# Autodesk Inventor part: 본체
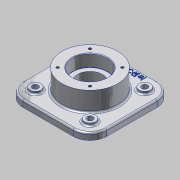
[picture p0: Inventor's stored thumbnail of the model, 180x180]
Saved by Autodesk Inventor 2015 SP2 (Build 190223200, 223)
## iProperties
Created: 2015-07
Part Number: 본체
Material: 알루미늄 6061
Document SubType Name: Modeling
Designer: AMC
Density: 2.7 g/cm^3
Appearance: 알루미늄 - 평지
Author: AMC
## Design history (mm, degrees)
sketch "스케치1"
  geometry: L1 (-75, -75)-(75, -75); L2 (75, -75)-(75, 75); L3 (75, 75)-(-75, 75); L4 (-75, 75)-(-75, -75); L5 (-75, -75)-(75, 75); L6 (75, -75)-(-75, 75); 1 further point
  constraints: 12 end point, 2 midpoint, 2 parallel, 1 horizontal, 1 perpendicular
  dimensions: "d0" = 150 distance of L3.end L2.end; "d1" = 150 distance of L2.end L1.end
extrude "돌출1" new body sketch "스케치1" distance "d2" = 12; taper "d3" = 0 deg
sketch "스케치2"
  geometry: C1 r 50 at (0, 0); 1 further point
  constraints: 1 centre point, 1 coincident
  dimensions: "d4" = 100 diameter of C1
extrude "돌출2" join sketch "스케치2" distance "d5" = 23; taper "d7" = 0 deg; dims "d6" = 47, "d8" = 0
fillet "모깎기1" dims "d9" = 30
sketch "스케치3"
  geometry: L1 (49, -49)-(-49, -49); L2 (-49, -49)-(-49, 49); L3 (-49, 49)-(49, 49); L4 (49, 49)-(49, -49); L5 (49, -49)-(-49, 49); L6 (-49, -49)-(49, 49); C1 r 10 at (-49, 49); 1 further point
  constraints: 12 end point, 2 midpoint, 2 parallel, 1 centre point, 1 coincident, 1 horizontal, 1 perpendicular
  dimensions: "d10" = 98 distance of L2.end L3.end; "d11" = 98 distance of L1.end L2.end; "d12" = 20 diameter of C1
extrude "돌출3" join sketch "스케치3" distance "d13" = 5; taper "d14" = 0 deg
hole "구멍1" diameter "d17" = 11; stored, may be unused: countersink angle "d21" = 90 deg, drill point angle "d23" = 118 deg; dims "d15" = 10, "d16" = 10, "d18" = 6, "d19" = 4, "d20" = 2, "d22" = 8
hole "구멍2" diameter "d29" = 62; stored, may be unused: countersink angle "d33" = 90 deg, drill point angle "d35" = 0 deg; dims "d27" = 10, "d28" = 10, "d30" = 6, "d31" = 4, "d32" = 2, "d34" = 22
hole "구멍3" diameter "d38" = 62; stored, may be unused: countersink angle "d42" = 90 deg, drill point angle "d44" = 0 deg; dims "d36" = 10, "d37" = 10, "d39" = 6, "d40" = 4, "d41" = 2, "d43" = 22
hole "구멍4" diameter "d47" = 45; stored, may be unused: countersink angle "d51" = 90 deg, drill point angle "d53" = 0 deg; dims "d45" = 10, "d46" = 10, "d48" = 6, "d49" = 4, "d50" = 2, "d52" = 22
sketch "스케치4"
  geometry: L1 (0, 0)-(-41, 0); L2 (0, 0)-(-28.991, 28.991); A1 r 41 centre (0, 0) between (-41, 0) and (-28.991, 28.991); 1 further point
  constraints: 4 end point, 2 point on circle, 1 centre point, 1 coincident, 1 horizontal
  dimensions: "d54" = 82 diameter of A1; "d55" = 45 deg angle of L2 L1
hole "구멍5" sketch "스케치4" at (-28.991, 28.991) diameter "d56" = 4.917; stored, may be unused: countersink angle "d60" = 90 deg, drill point angle "d62" = 118 deg; dims "d57" = 10, "d58" = 4, "d59" = 2, "d61" = 13
sketch "스케치5"
  geometry: L1 (0, 0)-(-41, 0); L2 (0, 0)-(-28.991, 28.991); A1 r 41 centre (0, 0) between (-41, 0) and (-28.991, 28.991); 1 further point
  constraints: 4 end point, 2 point on circle, 1 centre point, 1 coincident, 1 horizontal
  dimensions: "d63" = 82 diameter of A1; "d64" = 45 deg angle of L2 L1
hole "구멍6" sketch "스케치5" at (-28.991, 28.991) diameter "d65" = 4.917; stored, may be unused: countersink angle "d69" = 90 deg, drill point angle "d71" = 118 deg; dims "d66" = 10, "d67" = 4, "d68" = 2, "d70" = 13
fillet "모깎기2" dims "d78" = 3
fillet "모깎기3" dims "d79" = 0.3
chamfer "모따기1" distance "d80" = 1; stored, may be unused: second distance "d81" = 2, angle "d82" = 45 deg
sketch "스케치6"
  geometry: 2 further points
  constraints: 1 vertical alignment, 1 other
  dimensions: "d83" = 65 distance of point (0, 0) point (0, 65)
feature "엠보싱1" sketch "스케치6" dims "d10" = 98, "d11" = 98, "d12" = 20, "d84" = 1, "d85" = 0
node "솔리드1"
pattern_circular "원형 패턴1" dims angle "d25" = 360 deg
pattern_circular "원형 패턴2" dims angle "d73" = 360 deg
pattern_circular "원형 패턴3" dims angle "d76" = 360 deg
